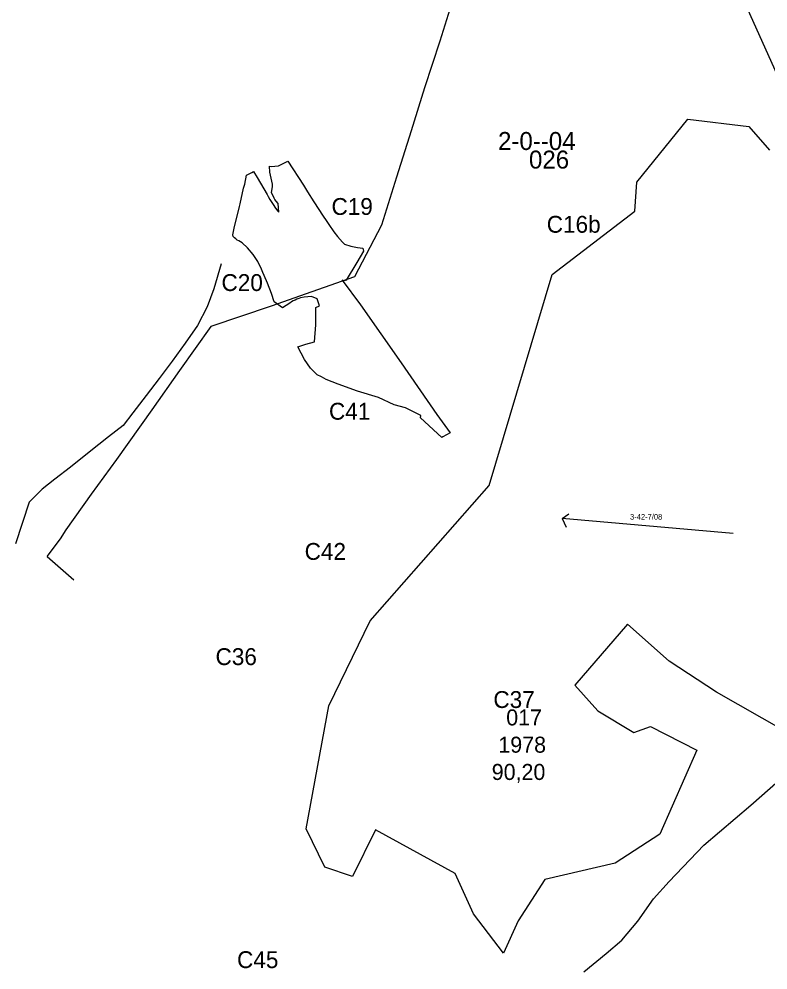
# Model space of a CAD drawing. Extents: x -557103 to -548162, y -1041918 to -1033974.
# Drawn here: x -553543 to -552210, y -1039045 to -1037353 of the extents above; entities that cross this region are included whole.
import ezdxf

# ---------------------------------------------------------------- set-up
doc = ezdxf.new("R2010")
doc.units = 0
for name, color, linetype in [('body3', 7, 'Continuous'), ('Vrstva 11', 7, 'Continuous'), ('Vrstva 14', 7, 'Continuous'), ('Vrstva 15', 7, 'Continuous'), ('Vrstva 16', 7, 'Continuous'), ('Vrstva 37', 7, 'Continuous'), ('Vrstva 9', 7, 'Continuous')]:
    doc.layers.add(name, color=color, linetype=linetype)

msp = doc.modelspace()

# ---------------------------------------------------------------- linework, layer by layer
at = {"layer": 'body3'}
for p, q in [((-553096.9, -1037626), (-553097.2, -1037615.2)), ((-553097.2, -1037615.2), (-553094.3, -1037616)), ((-553094.3, -1037616), (-553081, -1037614.7)), ((-553081, -1037614.7), (-553064.8, -1037606.2)), ((-553064.8, -1037606.2), (-553036.6, -1037649.2)), ((-553141.3, -1037647), (-553138.2, -1037631.4)), ((-553138.2, -1037631.4), (-553128.8, -1037626.6)), ((-553128.8, -1037626.6), (-553125.6, -1037624.9)), ((-553125.6, -1037624.9), (-553119.2, -1037635.3)), ((-553092.1, -1037647.5), (-553096.9, -1037626)), ((-553143.8, -1037654.3), (-553141.3, -1037647)), ((-553119.2, -1037635.3), (-553101.6, -1037665.4)), ((-553093.7, -1037662.3), (-553092, -1037651.9)), ((-553092, -1037651.9), (-553092.1, -1037647.5)), ((-553036.6, -1037649.2), (-553029.7, -1037660.7)), ((-553149.7, -1037682.2), (-553143.8, -1037654.3)), ((-553101.6, -1037665.4), (-553099.8, -1037669)), ((-553099.8, -1037669), (-553096.4, -1037674.6)), ((-553088.7, -1037672.3), (-553093.7, -1037662.3)), ((-553029.7, -1037660.7), (-553018.1, -1037678.9)), ((-553150.6, -1037686.8), (-553149.7, -1037682.2)), ((-553096.4, -1037674.6), (-553091, -1037683.3)), ((-553091, -1037683.3), (-553086.7, -1037689.7)), ((-553087.6, -1037674.3), (-553088.7, -1037672.3)), ((-553085.4, -1037677.4), (-553087.6, -1037674.3)), ((-553081.9, -1037681.7), (-553085.4, -1037677.4)), ((-553080.6, -1037697.1), (-553081.9, -1037681.7)), ((-553018.1, -1037678.9), (-553001.9, -1037704.3)), ((-553159.9, -1037725.3), (-553150.6, -1037686.8)), ((-553086.7, -1037689.7), (-553082.2, -1037695.1)), ((-553082.2, -1037695.1), (-553080.6, -1037697.1)), ((-553001.9, -1037704.3), (-552996.3, -1037711.7)), ((-552996.3, -1037711.7), (-552991.8, -1037718.9)), ((-552991.8, -1037718.9), (-552982.6, -1037731.8)), ((-553162.4, -1037737.3), (-553162.1, -1037734.2)), ((-553162.1, -1037734.2), (-553160.9, -1037728.3)), ((-553160.9, -1037728.3), (-553159.9, -1037725.3)), ((-552982.6, -1037731.8), (-552976.4, -1037740.4)), ((-553161.9, -1037740.3), (-553162.4, -1037737.3)), ((-553159.8, -1037742.7), (-553161.9, -1037740.3)), ((-553157.3, -1037744.8), (-553159.8, -1037742.7)), ((-553154.7, -1037746.7), (-553157.3, -1037744.8)), ((-553151.8, -1037748.2), (-553154.7, -1037746.7)), ((-553145.9, -1037751.5), (-553151.8, -1037748.2)), ((-553136.3, -1037760.6), (-553145.9, -1037751.5)), ((-552976.4, -1037740.4), (-552967.2, -1037750.2)), ((-552967.2, -1037750.2), (-552964, -1037753.9)), ((-553126.6, -1037772.4), (-553136.3, -1037760.6)), ((-552964, -1037753.9), (-552952.7, -1037757.8)), ((-552952.7, -1037757.8), (-552940.5, -1037759.7)), ((-552930, -1037766.3), (-552941.8, -1037786.9)), ((-552940.5, -1037759.7), (-552935.9, -1037760.3)), ((-552935.9, -1037760.3), (-552931.2, -1037761.4)), ((-552931.2, -1037761.4), (-552930, -1037766.3)), ((-553118.2, -1037785), (-553126.6, -1037772.4)), ((-553116.7, -1037787.6), (-553118.2, -1037785)), ((-552941.8, -1037786.9), (-552960.8, -1037817.8)), ((-553112.5, -1037795.8), (-553116.7, -1037787.6)), ((-553110.1, -1037801.4), (-553112.5, -1037795.8)), ((-553109.2, -1037804.2), (-553110.1, -1037801.4)), ((-553106.7, -1037809.6), (-553109.2, -1037804.2)), ((-553100.7, -1037823.3), (-553106.7, -1037809.6)), ((-552964.4, -1037819.3), (-552968, -1037817.8)), ((-552968, -1037817.8), (-552935.3, -1037861.8)), ((-552960.8, -1037817.8), (-552964.4, -1037819.3)), ((-553093.4, -1037841.8), (-553100.7, -1037823.3)), ((-553089.2, -1037856.6), (-553093.4, -1037841.8)), ((-553051.8, -1037853.5), (-553054.9, -1037855.1)), ((-553048.5, -1037852), (-553051.8, -1037853.5)), ((-553045.3, -1037850.6), (-553048.5, -1037852)), ((-553041.9, -1037849.6), (-553045.3, -1037850.6)), ((-553035.8, -1037848.2), (-553041.9, -1037849.6)), ((-553022.5, -1037846.9), (-553035.8, -1037848.2)), ((-553012.2, -1037851.5), (-553022.5, -1037846.9)), ((-553008, -1037863.9), (-553012.2, -1037851.5)), ((-553074.4, -1037867.1), (-553089.2, -1037856.6)), ((-553060.9, -1037858.8), (-553074.4, -1037867.1)), ((-553057.9, -1037856.9), (-553060.9, -1037858.8)), ((-553054.9, -1037855.1), (-553057.9, -1037856.9)), ((-553014.8, -1037866.8), (-553008, -1037863.9)), ((-553014.7, -1037897.5), (-553014.8, -1037866.8)), ((-552935.3, -1037861.8), (-552863.1, -1037965)), ((-553017.1, -1037927.6), (-553014.7, -1037897.5)), ((-553047, -1037936.9), (-553032.4, -1037931.8)), ((-553034.9, -1037959.4), (-553047, -1037936.9)), ((-553032.4, -1037931.8), (-553017.1, -1037927.6)), ((-553024.1, -1037974.9), (-553034.9, -1037959.4)), ((-552863.1, -1037965), (-552799.7, -1038057.3)), ((-553012.4, -1037986.5), (-553024.1, -1037974.9)), ((-553004.8, -1037990.3), (-553012.4, -1037986.5)), ((-552996.2, -1037994.8), (-553004.8, -1037990.3)), ((-552974.8, -1038003.3), (-552996.2, -1037994.8)), ((-552940.8, -1038015.6), (-552974.8, -1038003.3)), ((-552903.1, -1038026.6), (-552940.8, -1038015.6)), ((-552875.1, -1038040), (-552903.1, -1038026.6)), ((-552855, -1038045.2), (-552875.1, -1038040)), ((-552828.1, -1038059.1), (-552855, -1038045.2)), ((-552799.7, -1038057.3), (-552775.9, -1038089.4)), ((-552828.7, -1038063.2), (-552828.1, -1038059.1)), ((-552790.4, -1038098), (-552828.7, -1038063.2)), ((-552775.9, -1038089.4), (-552788.6, -1038096.9)), ((-552788.6, -1038096.9), (-552790.4, -1038098)), ((-552240.3, -1038752.1), (-552176.5, -1038695.8)), ((-552324.2, -1038823.4), (-552240.3, -1038752.1)), ((-552386.1, -1038887.7), (-552324.2, -1038823.4)), ((-552413.9, -1038918.7), (-552386.1, -1038887.7)), ((-552441.7, -1038958.3), (-552413.9, -1038918.7)), ((-552470.4, -1038992.3), (-552441.7, -1038958.3)), ((-552497.9, -1039016.2), (-552470.4, -1038992.3)), ((-552537.9, -1039048.6), (-552497.9, -1039016.2))]:
    msp.add_line(p, q, dxfattribs=at)
at = {"layer": 'Vrstva 11'}
msp.add_line((-552576.6, -1038241.9), (-552564.7, -1038233.6), dxfattribs=at)
msp.add_lwpolyline([(-552272.1, -1038268.6), (-552576.6, -1038241.9), (-552569.3, -1038257.5)], dxfattribs=at)
at = {"layer": 'Vrstva 14'}
msp.add_lwpolyline([(-551661.8, -1038633.9), (-553519.6, -1034507.2), (-553504.9, -1034676.5)], dxfattribs=at)
at = {"layer": 'Vrstva 15'}
for p, q in [((-552946.1, -1037812.1), (-553022.1, -1037838.9)), ((-553493.2, -1038309.6), (-553445.3, -1038351.1))]:
    msp.add_line(p, q, dxfattribs=at)
for points in [[(-552758.6, -1037278.6), (-552793.9, -1037392.6), (-552821.1, -1037475.8), (-552845.2, -1037552.1), (-552871.1, -1037634.9), (-552897.9, -1037720.2), (-552946.1, -1037812.1)], [(-553183.3, -1037788.8), (-553196.1, -1037833.5), (-553208.1, -1037865.3), (-553225.2, -1037899), (-553247.6, -1037929.9), (-553270.7, -1037962.2), (-553293.6, -1037992.9), (-553317, -1038023.5), (-553340.4, -1038054.1), (-553357.4, -1038076.9), (-553383.9, -1038097.1), (-553418, -1038124), (-553451.7, -1038150.5), (-553479.5, -1038172.2), (-553502.1, -1038190), (-553525.2, -1038212.9), (-553549.1, -1038287.3)], [(-553022.1, -1037838.9), (-553094.1, -1037864.3), (-553201.4, -1037900.8)], [(-553201.4, -1037900.8), (-553257.3, -1037979), (-553306.4, -1038048.8), (-553369.7, -1038137.3), (-553414.4, -1038199), (-553459.8, -1038262.5), (-553469.8, -1038278), (-553493.7, -1038309.6)]]:
    msp.add_lwpolyline(points, dxfattribs=at)
at = {"layer": 'Vrstva 9'}
msp.add_lwpolyline([(-552181.9, -1038619.5), (-552301.5, -1038551.3), (-552386.1, -1038496.1), (-552459.8, -1038429.9), (-552553.6, -1038538.5), (-552513.1, -1038584.5), (-552448.7, -1038623.1), (-552419.3, -1038612.1), (-552336.5, -1038654.4), (-552402.7, -1038803.5), (-552481.8, -1038855.1), (-552607, -1038884.5), (-552654.8, -1038958.2), (-552680.6, -1039015.2), (-552734, -1038945.3), (-552767.1, -1038873.5), (-552908.8, -1038796.2), (-552949.3, -1038879), (-552999, -1038862.4), (-553032.1, -1038794.3), (-552991.6, -1038575.3), (-552918, -1038424.3), (-552706.4, -1038183.2), (-552594.1, -1037807.7), (-552446.9, -1037695.4), (-552443.2, -1037643.8), (-552353, -1037531.5), (-552244.4, -1037544.4), (-552207.6, -1037586.8)], dxfattribs=at)

# ---------------------------------------------------------------- texts
at = {"layer": 'Vrstva 11'}
msp.add_text('3-42-7/08', height=10, dxfattribs=at).set_placement((-552455.5, -1038244.1))
at = {"layer": 'Vrstva 16'}
for s, p in [('2-0--04', (-552690.5, -1037586.5)), ('026', (-552635.4, -1037619.5))]:
    msp.add_text(s, height=32, dxfattribs=at).set_placement(p)
at = {"layer": 'Vrstva 37'}
for s, p in [('C19', (-552986.9, -1037702)), ('C16b', (-552603.8, -1037733.7)), ('C20', (-553182.7, -1037837.4)), ('C41', (-552991.4, -1038066.3)), ('C42', (-553034.7, -1038315.7)), ('C36', (-553193.3, -1038502.9)), ('C37', (-552698.8, -1038579.2)), ('C45', (-553155, -1039042))]:
    msp.add_text(s, height=30, dxfattribs=at).set_placement(p)
at = {"layer": 'Vrstva 9'}
for s, p in [('017', (-552675.9, -1038610.3)), ('1978', (-552689.9, -1038658.8)), ('90,20', (-552701.7, -1038707.3))]:
    msp.add_text(s, height=28.5, dxfattribs=at).set_placement(p)

doc.saveas('drawing.dxf')
